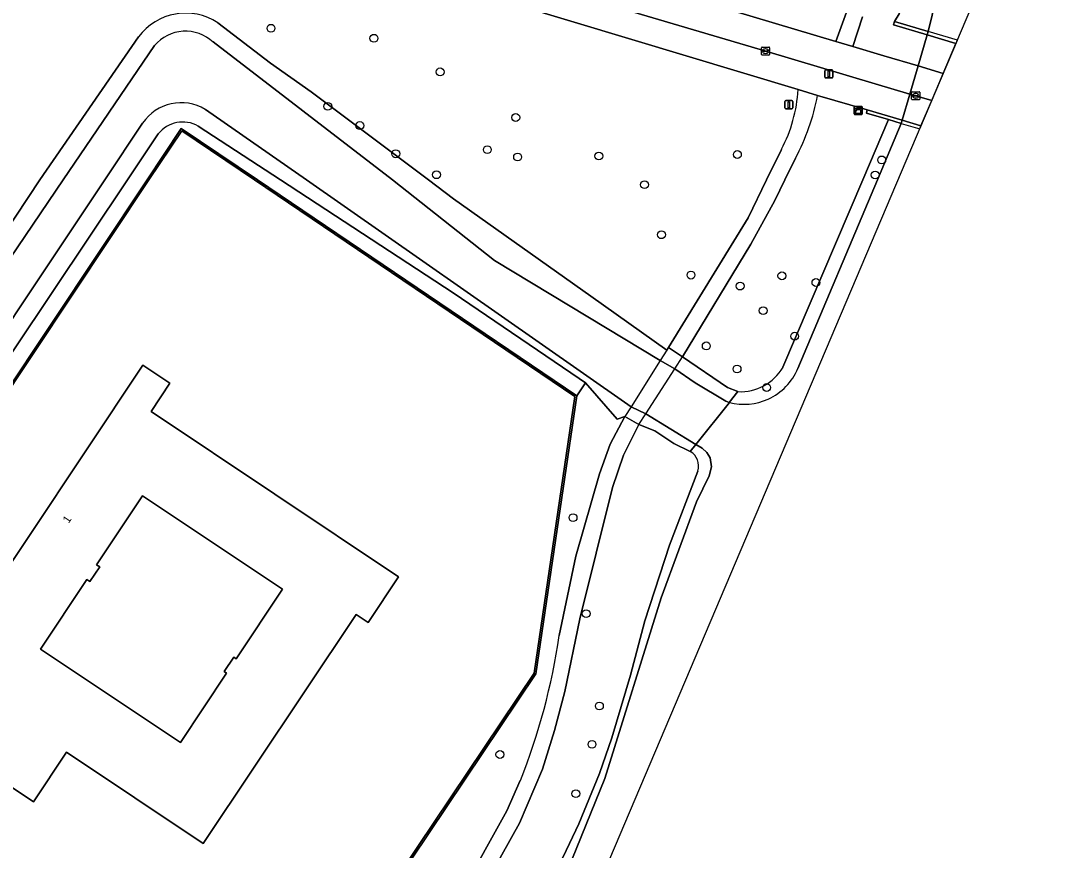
# Model space of a CAD drawing. Extents: x 160157 to 160921, y 381516 to 382045.
# Drawn here: x 160791.5 to 160921, y 381666.3 to 381769.9 of the extents above; entities that cross this region are included whole.
import ezdxf

# ---------------------------------------------------------------- set-up
doc = ezdxf.new("R2010")
doc.units = 0
for name, color, linetype in [('IMGEO_Berm_groen', 7, 'Continuous'), ('IMGEO_Boom', 7, 'Continuous'), ('IMGEO_Dek', 7, 'Continuous'), ('IMGEO_Erf', 7, 'Continuous'), ('IMGEO_Fietspad_gesloten', 7, 'Continuous'), ('IMGEO_Fietspad_open', 7, 'Continuous'), ('IMGEO_Grasland_overig', 7, 'Continuous'), ('IMGEO_Groenvoorziening', 7, 'Continuous'), ('IMGEO_Kast', 7, 'Continuous'), ('IMGEO_Kolk', 7, 'Continuous'), ('IMGEO_Lichtmast', 7, 'Continuous'), ('IMGEO_Loofbos', 7, 'Continuous'), ('IMGEO_Muur', 7, 'Continuous'), ('IMGEO_Oever', 7, 'Continuous'), ('IMGEO_Pand', 7, 'Continuous'), ('IMGEO_Pand_nummerreeks', 7, 'Continuous'), ('IMGEO_Verkeersbordpaal', 7, 'Continuous'), ('IMGEO_Voetpad_gesloten', 7, 'Continuous'), ('IMGEO_Voetpad_open', 7, 'Continuous'), ('IMGEO_Waterloop', 7, 'Continuous')]:
    doc.layers.add(name, color=color, linetype=linetype)

msp = doc.modelspace()

# ---------------------------------------------------------------- linework, layer by layer
at = {"layer": 'IMGEO_Berm_groen'}
for points in [[(160823.24, 381789.06), (160836.93, 381784.15), (160893.31, 381767.3), (160894.66, 381770.94)], [(160896.67, 381770.38), (160895.43, 381766.66), (160899.33, 381765.5), (160903.6, 381764.23), (160904.74, 381768.11), (160900.52, 381769.38), (160900.65, 381769.8), (160901.23, 381770.74), (160904.69, 381783.05), (160904.31, 381786.03)]]:
    msp.add_lwpolyline(points, dxfattribs=at)
msp.add_lwpolyline([(160906.74, 381763.29), (160908.33, 381767.03), (160904.74, 381768.11), (160903.6, 381764.23)], close=True, dxfattribs=at)
at = {"layer": 'IMGEO_Boom'}
for centre in [(160822.76, 381768.94), (160835.62, 381767.69), (160843.89, 381763.49), (160829.86, 381759.19), (160853.34, 381757.8), (160833.86, 381756.79), (160849.79, 381753.78), (160838.35, 381753.27), (160853.57, 381752.86), (160863.72, 381752.99), (160881.03, 381753.17), (160899.06, 381752.5), (160843.44, 381750.65), (160898.24, 381750.62), (160869.43, 381749.41), (160871.54, 381743.16), (160875.23, 381738.12), (160886.59, 381738.03), (160881.37, 381736.75), (160890.84, 381737.19), (160884.25, 381733.68), (160888.18, 381730.49), (160877.14, 381729.28), (160880.99, 381726.39), (160884.68, 381724.08), (160860.5, 381707.84), (160862.13, 381695.85), (160863.79, 381684.32), (160862.87, 381679.53), (160851.36, 381678.26), (160860.85, 381673.37)]:
    msp.add_circle(centre, 0.489, dxfattribs=at)
at = {"layer": 'IMGEO_Dek'}
for points in [[(160903.8, 381756.38), (160908.51, 381767.45), (160908.51, 381767.45), (160904.87, 381768.54), (160904.74, 381768.11), (160903.6, 381764.23), (160902.56, 381760.73), (160901.6, 381757.46), (160901.48, 381757.06)], [(160873.2, 381726.4), (160874.19, 381727.93), (160872.42, 381729.06), (160872.22, 381728.75), (160871.4, 381727.46), (160867.75, 381721.69), (160866.97, 381720.46), (160868.73, 381719.46), (160869.6, 381720.8)]]:
    msp.add_lwpolyline(points, close=True, dxfattribs=at)
at = {"layer": 'IMGEO_Erf'}
for points in [[(160860.74, 381722.95), (160820.71, 381750), (160811.61, 381756.15), (160807.52, 381750), (160783.35, 381713.75), (160783.57, 381713.6), (160780.89, 381709.53), (160780.66, 381709.64), (160746.07, 381658.25), (160790.57, 381616.68), (160820.21, 381635.63), (160855.65, 381688.4)], [(160838.71, 381700.46), (160834.9, 381694.76), (160833.4, 381695.76), (160814.29, 381667.15), (160797.21, 381678.55), (160793.08, 381672.36), (160782.77, 381679.24), (160786.86, 381685.37), (160778.89, 381690.69), (160780.07, 381692.46), (160777.63, 381694.09), (160779.06, 381696.23), (160781.46, 381694.63), (160782.65, 381696.41), (160785.26, 381694.66), (160806.77, 381726.87), (160810.13, 381724.62), (160807.78, 381721.1)], [(160824.21, 381698.89), (160806.73, 381710.56), (160800.98, 381701.95), (160801.38, 381701.69), (160800.15, 381699.85), (160799.77, 381700.11), (160793.97, 381691.42), (160811.44, 381679.76), (160817.21, 381688.4), (160816.9, 381688.61), (160818.11, 381690.42), (160818.42, 381690.21)]]:
    msp.add_lwpolyline(points, close=True, dxfattribs=at)
at = {"layer": 'IMGEO_Fietspad_gesloten'}
msp.add_lwpolyline([(160905.31, 381759.91), (160906.74, 381763.29), (160903.6, 381764.23), (160902.56, 381760.73)], close=True, dxfattribs=at)
at = {"layer": 'IMGEO_Fietspad_open'}
msp.add_lwpolyline([(160820.77, 381786.23), (160825.69, 381784.41), (160838.2, 381780.05), (160845.08, 381777.86), (160864.68, 381771.96), (160884.57, 381766.08), (160898.25, 381762.01), (160902.56, 381760.73), (160903.6, 381764.23), (160899.33, 381765.5), (160895.43, 381766.66), (160893.31, 381767.3), (160836.93, 381784.15), (160823.24, 381789.06)], dxfattribs=at)
at = {"layer": 'IMGEO_Grasland_overig'}
for points in [[(160886.72, 381726.62), (160896.7, 381750), (160899.91, 381757.53), (160897.17, 381758.34), (160897.25, 381758.77), (160891.04, 381760.56)], [(160888.28, 381752.71), (160886.96, 381750), (160885.71, 381747.43), (160882.69, 381742), (160874.19, 381727.93), (160879.78, 381724.07), (160881.1, 381723.58)]]:
    msp.add_lwpolyline(points, dxfattribs=at)
for centre, radius, start, end in [((160863.94, 381765.69), 27.58, 331.9381, 349.2835), ((160881.42, 381729.7), 6.14, 267.0172, 329.8247)]:
    msp.add_arc(centre, radius, start, end, dxfattribs=at)
at = {"layer": 'IMGEO_Groenvoorziening'}
for points in [[(160845.52, 381735.91), (160823.96, 381750), (160813.67, 381756.72)], [(160808.67, 381755.74), (160804.82, 381750), (160781.27, 381714.84), (160782.76, 381713.72), (160782.96, 381714.02), (160783.19, 381713.86), (160807.28, 381750), (160811.56, 381756.43), (160821.07, 381750), (160860.96, 381723.05), (160862.07, 381724.67), (160861.27, 381725.22), (160845.52, 381735.91)], [(160860.83, 381703.04), (160863.81, 381713.3), (160865.13, 381716.99), (160866.97, 381720.46), (160866.02, 381720.14), (160862.07, 381724.67), (160860.96, 381723.05), (160855.84, 381688.32), (160820.35, 381635.48), (160790.55, 381616.43), (160789.53, 381615.69), (160791.95, 381613.46), (160793.53, 381614), (160806.92, 381622.08), (160812.28, 381625.56), (160815.77, 381628.23), (160833.62, 381644.48), (160837.29, 381648.09), (160840.52, 381652.1), (160846.58, 381661.03), (160852.21, 381671.21), (160853.91, 381675.02)], [(160875.14, 381716.09), (160873.1, 381717.09), (160870.72, 381718.69), (160868.73, 381719.46), (160866.82, 381715.63), (160865.41, 381711.6), (160861.34, 381695.19), (160859.49, 381686.11), (160858.2, 381681.25), (160856.69, 381676.45), (160853.81, 381669.7), (160848.2, 381659.61), (160842.12, 381651.05), (160838.4, 381646.23), (160843.55, 381645.32), (160851.86, 381653.79), (160854.68, 381657.51), (160857.15, 381661.47), (160859.28, 381665.49), (160861.24, 381669.59), (160863.79, 381675.87), (160865.35, 381680.36), (160867.68, 381688.15)], [(160867.68, 381688.15), (160869.48, 381694.94), (160872.54, 381704.38), (160876.09, 381713.66)], [(160858.78, 381693.12), (160860.83, 381703.04)]]:
    msp.add_lwpolyline(points, dxfattribs=at)
for centre, radius, start, end in [((160811.75, 381753.29), 3.94, 60.7744, 141.4883), ((160874.11, 381714.29), 2.08, 342.1586, 60.1244), ((160778.3, 381705.04), 81.36, 338.3447, 351.5735)]:
    msp.add_arc(centre, radius, start, end, dxfattribs=at)
at = {"layer": 'IMGEO_Kast'}
for p, q in [((160895.62, 381758.26), (160895.62, 381759.1)), ((160895.62, 381759.1), (160895.62, 381758.26)), ((160895.69, 381759.18), (160896.54, 381759.18)), ((160896.54, 381759.18), (160895.69, 381759.18)), ((160896.62, 381759.11), (160896.62, 381758.27)), ((160896.62, 381758.27), (160896.62, 381759.11)), ((160896.55, 381758.18), (160895.7, 381758.18)), ((160895.7, 381758.18), (160896.55, 381758.18))]:
    msp.add_line(p, q, dxfattribs=at)
for points in [[(160895.82, 381758.97), (160896.42, 381758.97), (160896.42, 381758.89), (160895.82, 381758.89), (160895.82, 381758.97)], [(160895.82, 381758.8), (160896.42, 381758.8), (160896.42, 381758.31), (160895.82, 381758.31), (160895.82, 381758.8)]]:
    msp.add_lwpolyline(points, dxfattribs=at)
msp.add_circle((160895.9, 381758.65), 0.0377, dxfattribs=at)
for centre, start, end in [((160895.7, 381759.1), 92.4484, 184.2845), ((160895.7, 381759.1), 92.4484, 184.2845), ((160896.54, 381759.1), 2.4484, 94.2845), ((160896.54, 381759.1), 2.4484, 94.2845), ((160895.7, 381758.26), 182.4484, 274.2845), ((160895.7, 381758.26), 182.4484, 274.2845), ((160896.54, 381758.26), 272.4484, 4.2845), ((160896.54, 381758.26), 272.4484, 4.2845)]:
    msp.add_arc(centre, 0.0779, start, end, dxfattribs=at)
at = {"layer": 'IMGEO_Kolk'}
for p, q in [((160884.05, 381765.66), (160884.05, 381766.51)), ((160884.12, 381766.59), (160884.97, 381766.59)), ((160884.97, 381765.58), (160884.12, 381765.58)), ((160884.3, 381766.08), (160884.3, 381766.09)), ((160884.74, 381766.04), (160884.34, 381766.04)), ((160884.35, 381766.13), (160884.74, 381766.13)), ((160884.53, 381766.36), (160884.56, 381766.36)), ((160884.56, 381765.81), (160884.53, 381765.81)), ((160884.79, 381766.09), (160884.79, 381766.08)), ((160885.05, 381766.51), (160885.05, 381765.66)), ((160902.8, 381760.08), (160902.8, 381760.94)), ((160902.88, 381761.01), (160903.73, 381761.01)), ((160903.06, 381760.5), (160903.06, 381760.52)), ((160903.5, 381760.47), (160903.1, 381760.47)), ((160903.11, 381760.55), (160903.5, 381760.55)), ((160903.29, 381760.79), (160903.32, 381760.79)), ((160903.55, 381760.52), (160903.55, 381760.5)), ((160903.81, 381760.94), (160903.81, 381760.08)), ((160903.73, 381760.01), (160902.88, 381760.01)), ((160903.31, 381760.23), (160903.29, 381760.23))]:
    msp.add_line(p, q, dxfattribs=at)
for points in [[(160884.05, 381765.66), (160884.05, 381766.51)], [(160884.12, 381766.59), (160884.97, 381766.59)], [(160884.97, 381765.58), (160884.12, 381765.58)], [(160885.05, 381766.51), (160885.05, 381765.66)], [(160902.8, 381760.08), (160902.8, 381760.94)], [(160902.88, 381761.01), (160903.73, 381761.01)], [(160903.81, 381760.94), (160903.81, 381760.08)], [(160903.73, 381760.01), (160902.88, 381760.01)]]:
    msp.add_lwpolyline(points, dxfattribs=at)
for centre, radius, start, end in [((160884.12, 381766.51), 0.0765, 91.552, 178.448), ((160884.12, 381766.51), 0.0765, 91.552, 178.448), ((160884.12, 381765.66), 0.0765, 181.552, 268.448), ((160884.12, 381765.66), 0.0765, 181.552, 268.448), ((160884.34, 381766.09), 0.0403, 85.8775, 175.7526), ((160884.34, 381766.08), 0.0366, 178.938, 274.7102), ((160884.75, 381766.09), 0.0386, 1.7309, 96.639), ((160884.75, 381766.08), 0.043, 264.8664, 352.4533), ((160884.97, 381766.51), 0.0765, 1.552, 88.448), ((160884.97, 381766.51), 0.0765, 1.552, 88.448), ((160884.97, 381765.66), 0.0765, 271.552, 358.448), ((160884.97, 381765.66), 0.0765, 271.552, 358.448), ((160902.88, 381760.93), 0.0765, 91.552, 178.448), ((160902.88, 381760.93), 0.0765, 91.552, 178.448), ((160903.1, 381760.51), 0.0403, 85.8775, 175.7526), ((160903.1, 381760.5), 0.0366, 178.938, 274.7102), ((160903.51, 381760.51), 0.0386, 1.7309, 96.639), ((160903.5, 381760.51), 0.043, 264.8664, 352.4533), ((160903.73, 381760.93), 0.0765, 1.552, 88.448), ((160903.73, 381760.93), 0.0765, 1.552, 88.448), ((160902.88, 381760.09), 0.0765, 181.552, 268.448), ((160902.88, 381760.09), 0.0765, 181.552, 268.448), ((160903.73, 381760.09), 0.0765, 271.552, 358.448), ((160903.73, 381760.09), 0.0765, 271.552, 358.448)]:
    msp.add_arc(centre, radius, start, end, dxfattribs=at)
for centre, major_axis, ratio, start_param, end_param in [((160884.53, 381766.08), (-0.387, 0.002), 0.722429, 4.712389, 7.853982), ((160884.56, 381766.08), (-0.39, 0.002), 0.717154, 1.570796, 4.712389), ((160903.29, 381760.51), (-0.387, 0.002), 0.722429, 4.712389, 7.853982), ((160903.32, 381760.51), (-0.39, 0.002), 0.717154, 1.570796, 4.712389)]:
    msp.add_ellipse(centre, major_axis=major_axis, ratio=ratio, start_param=start_param, end_param=end_param, dxfattribs=at)
at = {"layer": 'IMGEO_Lichtmast'}
for p, q in [((160891.96, 381762.84), (160891.96, 381763.64)), ((160891.96, 381763.64), (160891.96, 381762.84)), ((160892.06, 381763.74), (160892.85, 381763.74)), ((160892.85, 381763.74), (160892.06, 381763.74)), ((160892.95, 381763.64), (160892.95, 381762.84)), ((160892.95, 381762.84), (160892.95, 381763.64)), ((160892.85, 381762.74), (160892.06, 381762.74)), ((160892.06, 381762.74), (160892.85, 381762.74))]:
    msp.add_line(p, q, dxfattribs=at)
msp.add_lwpolyline([(160892.38, 381763.62), (160892.53, 381763.62), (160892.53, 381762.87), (160892.38, 381762.87), (160892.38, 381763.62)], dxfattribs=at)
for centre, start, end in [((160892.06, 381763.64), 90, 180), ((160892.06, 381763.64), 90, 180), ((160892.85, 381763.64), 0, 90), ((160892.85, 381763.64), 360, 90), ((160892.06, 381762.84), 180, 270), ((160892.06, 381762.84), 180, 270), ((160892.85, 381762.84), 270, 0), ((160892.85, 381762.84), 270, 0)]:
    msp.add_arc(centre, 0.1, start, end, dxfattribs=at)
at = {"layer": 'IMGEO_Loofbos'}
for points in [[(160798.59, 381790.38), (160797.76, 381789.74), (160795.51, 381787.72), (160792.76, 381789.48), (160791.43, 381788.02), (160767.52, 381753.72), (160764.92, 381750), (160753.58, 381733.81), (160755.22, 381732.74), (160764.09, 381726.92), (160772.58, 381721.3), (160774.15, 381720.21), (160793.89, 381750), (160806.2, 381767.87)], [(160888.61, 381761.28), (160839.44, 381776.11), (160820.7, 381782.66), (160805.66, 381788.42), (160801.4, 381790.42)], [(160816.13, 381769.62), (160822.7, 381764.59), (160827.8, 381761.01), (160842.45, 381750), (160845.57, 381747.65), (160862.73, 381735.48), (160872.22, 381728.75), (160872.42, 381729.06), (160882.38, 381745.29), (160884.67, 381750), (160886.53, 381753.82)]]:
    msp.add_lwpolyline(points, dxfattribs=at)
for centre, radius, start, end in [((160812.1, 381763.47), 7.36, 56.7615, 143.3065), ((160870.48, 381762.31), 18.16, 332.1383, 356.7516)]:
    msp.add_arc(centre, radius, start, end, dxfattribs=at)
at = {"layer": 'IMGEO_Muur'}
for points in [[(160900.65, 381769.8), (160900.52, 381769.38), (160904.74, 381768.11), (160904.87, 381768.54)], [(160908.51, 381767.45), (160908.51, 381767.45), (160904.87, 381768.54), (160904.74, 381768.11), (160908.33, 381767.03)], [(160897.25, 381758.77), (160897.17, 381758.34), (160899.91, 381757.53), (160901.48, 381757.06), (160901.6, 381757.46)], [(160903.96, 381756.75), (160901.6, 381757.46), (160901.48, 381757.06), (160903.8, 381756.38)], [(160821.07, 381750), (160811.56, 381756.43), (160807.28, 381750), (160783.19, 381713.86), (160783.35, 381713.75), (160807.52, 381750), (160811.61, 381756.15), (160820.71, 381750), (160860.74, 381722.95), (160855.65, 381688.4), (160820.21, 381635.63), (160790.57, 381616.68), (160746.07, 381658.25), (160780.66, 381709.64), (160780.48, 381709.73), (160745.81, 381658.22), (160790.55, 381616.43), (160820.35, 381635.48), (160855.84, 381688.32), (160860.96, 381723.05)]]:
    msp.add_lwpolyline(points, close=True, dxfattribs=at)
at = {"layer": 'IMGEO_Oever'}
msp.add_lwpolyline([(160911.32, 381792.4), (160907.63, 381793.53), (160904.69, 381783.05), (160901.23, 381770.74), (160900.65, 381769.8), (160904.87, 381768.54), (160906.31, 381774.51)], close=True, dxfattribs=at)
for points in [[(160880.02, 381722.23), (160881.1, 381723.58), (160879.78, 381724.07), (160874.19, 381727.93), (160872.42, 381729.06), (160872.22, 381728.75), (160862.73, 381735.48), (160845.57, 381747.65), (160842.45, 381750), (160827.8, 381761.01), (160822.7, 381764.59), (160816.13, 381769.62)], [(160806.2, 381767.87), (160793.89, 381750), (160774.15, 381720.21), (160775.76, 381719), (160796.82, 381750), (160808.22, 381766.79)], [(160815.52, 381767.23), (160837.93, 381750), (160850.68, 381739.95), (160862.36, 381732.91), (160871.4, 381727.46), (160873.2, 381726.4), (160875.76, 381724.65), (160879.58, 381722.36), (160879.8, 381722.29), (160880.02, 381722.23)], [(160875.14, 381716.09), (160875.84, 381716.97), (160869.6, 381720.8), (160867.75, 381721.69), (160861.4, 381726.12), (160827.18, 381750), (160814.56, 381758.8)], [(160806.73, 381757.1), (160801.99, 381750), (160779.43, 381716.23), (160781.27, 381714.84), (160804.82, 381750), (160808.67, 381755.74)], [(160813.67, 381756.72), (160823.96, 381750), (160845.52, 381735.91), (160861.27, 381725.22), (160862.07, 381724.67), (160866.02, 381720.14), (160866.97, 381720.46), (160868.73, 381719.46), (160870.72, 381718.69), (160873.1, 381717.09), (160875.14, 381716.09)], [(160901.48, 381757.06), (160899.91, 381757.53), (160896.7, 381750), (160886.72, 381726.62)], [(160888.57, 381726.47), (160898.54, 381750), (160901.48, 381757.06)], [(160881.1, 381723.58), (160880.02, 381722.23), (160880.03, 381722.23)], [(160800.26, 381605.88), (160812.69, 381614.8), (160818.68, 381619.39), (160824.35, 381624.7), (160830.52, 381630.47), (160847.44, 381647), (160854.41, 381655.52), (160858.26, 381660.7), (160859.19, 381662.23), (160864.45, 381675.26), (160871.51, 381697.83), (160875.93, 381709.79), (160877.51, 381713.07), (160877.78, 381714.17), (160877.63, 381715.3), (160877.2, 381715.96), (160876.61, 381716.5), (160875.85, 381716.96), (160875.84, 381716.97), (160875.14, 381716.09)], [(160876.09, 381713.66), (160872.54, 381704.38), (160869.48, 381694.94), (160867.68, 381688.15), (160865.35, 381680.36), (160863.79, 381675.87), (160861.24, 381669.59), (160859.28, 381665.49), (160857.15, 381661.47), (160854.68, 381657.51), (160851.86, 381653.79), (160843.55, 381645.32), (160829.6, 381631.5), (160821.82, 381624.23), (160818.15, 381621.1), (160815.79, 381618.73), (160813.53, 381617.06), (160809.43, 381614.59), (160800.34, 381607.9)]]:
    msp.add_lwpolyline(points, dxfattribs=at)
for centre, radius, start, end in [((160812.1, 381763.47), 7.36, 56.7615, 143.3065), ((160812.08, 381763.55), 5.03, 46.8692, 140.0303), ((160811.53, 381753.85), 5.8, 58.5511, 145.945), ((160811.75, 381753.29), 3.94, 60.7744, 141.4883), ((160881.42, 381729.7), 6.14, 267.0172, 329.8247), ((160881.88, 381729.23), 7.24, 294.5608, 337.5901), ((160881.87, 381729.23), 7.24, 255.3183, 294.5997), ((160874.11, 381714.29), 2.08, 342.1586, 60.1244)]:
    msp.add_arc(centre, radius, start, end, dxfattribs=at)
at = {"layer": 'IMGEO_Pand'}
for points in [[(160833.4, 381695.76), (160834.9, 381694.76), (160838.71, 381700.46), (160807.78, 381721.1), (160810.13, 381724.62), (160806.77, 381726.87), (160785.26, 381694.66), (160782.65, 381696.41), (160781.46, 381694.63), (160779.06, 381696.23), (160777.63, 381694.09), (160780.07, 381692.46), (160778.89, 381690.69), (160786.86, 381685.37), (160782.77, 381679.24), (160793.08, 381672.36), (160797.21, 381678.55), (160814.29, 381667.15)], [(160799.77, 381700.11), (160800.15, 381699.85), (160801.38, 381701.69), (160800.98, 381701.95), (160806.73, 381710.56), (160824.21, 381698.89), (160818.42, 381690.21), (160818.11, 381690.42), (160816.9, 381688.61), (160817.21, 381688.4), (160811.44, 381679.76), (160793.97, 381691.42)]]:
    msp.add_lwpolyline(points, close=True, dxfattribs=at)
at = {"layer": 'IMGEO_Verkeersbordpaal'}
for p, q in [((160886.96, 381759), (160886.96, 381759.8)), ((160886.96, 381759.8), (160886.96, 381759)), ((160887.06, 381759.9), (160887.85, 381759.9)), ((160887.85, 381759.9), (160887.06, 381759.9)), ((160887.95, 381759.8), (160887.95, 381759)), ((160887.95, 381759), (160887.95, 381759.8)), ((160887.85, 381758.9), (160887.06, 381758.9)), ((160887.06, 381758.9), (160887.85, 381758.9))]:
    msp.add_line(p, q, dxfattribs=at)
msp.add_lwpolyline([(160887.38, 381759.77), (160887.53, 381759.77), (160887.53, 381759.02), (160887.38, 381759.02), (160887.38, 381759.77)], dxfattribs=at)
for centre, start, end in [((160887.06, 381759.8), 90, 180), ((160887.06, 381759.8), 90, 180), ((160887.85, 381759.8), 0, 90), ((160887.85, 381759.8), 360, 90), ((160887.06, 381759), 180, 270), ((160887.06, 381759), 180, 270), ((160887.85, 381759), 270, 0), ((160887.85, 381759), 270, 0)]:
    msp.add_arc(centre, 0.1, start, end, dxfattribs=at)
at = {"layer": 'IMGEO_Voetpad_gesloten'}
for points in [[(160891.04, 381760.56), (160888.61, 381761.28)], [(160886.53, 381753.82), (160884.67, 381750), (160882.38, 381745.29), (160872.42, 381729.06), (160874.19, 381727.93), (160882.69, 381742), (160885.71, 381747.43), (160886.96, 381750), (160888.28, 381752.71)], [(160810.37, 381621.8), (160816.14, 381625.62), (160821.18, 381629.94), (160838.4, 381646.23), (160842.12, 381651.05), (160848.2, 381659.61), (160853.81, 381669.7), (160856.69, 381676.45), (160858.2, 381681.25), (160859.49, 381686.11), (160861.34, 381695.19), (160865.41, 381711.6), (160866.82, 381715.63), (160868.73, 381719.46), (160866.97, 381720.46), (160865.13, 381716.99), (160863.81, 381713.3), (160860.83, 381703.04), (160858.78, 381693.12)], [(160853.91, 381675.02), (160852.21, 381671.21), (160846.58, 381661.03), (160840.52, 381652.1), (160837.29, 381648.09), (160833.62, 381644.48), (160815.77, 381628.23), (160812.28, 381625.56), (160806.92, 381622.08), (160793.53, 381614), (160791.95, 381613.46), (160791.56, 381613.33), (160791.58, 381613.07), (160792.92, 381611.91), (160793.01, 381611.67), (160793.58, 381612.11), (160796.34, 381613.41), (160802.5, 381616.82), (160810.37, 381621.8)]]:
    msp.add_lwpolyline(points, dxfattribs=at)
msp.add_lwpolyline([(160873.2, 381726.4), (160874.19, 381727.93), (160872.42, 381729.06), (160872.22, 381728.75), (160871.4, 381727.46), (160867.75, 381721.69), (160866.97, 381720.46), (160868.73, 381719.46), (160869.6, 381720.8)], close=True, dxfattribs=at)
for centre, radius, start, end in [((160870.48, 381762.31), 18.16, 332.1383, 356.7516), ((160863.94, 381765.69), 27.58, 331.9381, 349.2835), ((160778.3, 381705.04), 81.36, 338.3447, 351.5735)]:
    msp.add_arc(centre, radius, start, end, dxfattribs=at)
at = {"layer": 'IMGEO_Voetpad_open'}
for points in [[(160801.4, 381790.42), (160805.66, 381788.42), (160820.7, 381782.66), (160839.44, 381776.11), (160888.61, 381761.28), (160891.04, 381760.56), (160897.25, 381758.77), (160901.6, 381757.46), (160902.56, 381760.73), (160898.25, 381762.01), (160884.57, 381766.08), (160864.68, 381771.96), (160845.08, 381777.86)], [(160894.66, 381770.94), (160893.31, 381767.3), (160895.43, 381766.66), (160896.67, 381770.38)]]:
    msp.add_lwpolyline(points, dxfattribs=at)
msp.add_lwpolyline([(160905.31, 381759.91), (160902.56, 381760.73), (160901.6, 381757.46), (160903.96, 381756.75)], close=True, dxfattribs=at)
at = {"layer": 'IMGEO_Waterloop'}
for points in [[(160775.77, 381559.99), (160807.03, 381606.26), (160859.46, 381652.02), (160920.99, 381796.82), (160913.25, 381799.3), (160913.21, 381799.16), (160913, 381798.38), (160912.77, 381797.57), (160911.98, 381794.75), (160911.46, 381792.9), (160911.32, 381792.4), (160906.31, 381774.51), (160904.87, 381768.54), (160904.74, 381768.11), (160903.6, 381764.23), (160902.56, 381760.73), (160901.6, 381757.46), (160901.48, 381757.06), (160898.54, 381750), (160888.57, 381726.47)], [(160814.56, 381758.8), (160827.18, 381750), (160861.4, 381726.12), (160867.75, 381721.69), (160869.6, 381720.8), (160875.84, 381716.97), (160875.85, 381716.96), (160880.03, 381722.23), (160880.02, 381722.23), (160879.8, 381722.29), (160879.58, 381722.36), (160875.76, 381724.65), (160873.2, 381726.4), (160871.4, 381727.46), (160862.36, 381732.91), (160850.68, 381739.95), (160837.93, 381750), (160815.52, 381767.23)], [(160808.22, 381766.79), (160796.82, 381750), (160775.76, 381719), (160775.56, 381718.69), (160773.59, 381715.62), (160773.42, 381715.35), (160736.36, 381661.51)], [(160777.45, 381712.45), (160777.61, 381712.77), (160779.27, 381715.92), (160779.43, 381716.23), (160801.99, 381750), (160806.73, 381757.1)], [(160880.03, 381722.23), (160875.85, 381716.96), (160876.61, 381716.5), (160877.2, 381715.96), (160877.63, 381715.3), (160877.78, 381714.17), (160877.51, 381713.07), (160875.93, 381709.79), (160871.51, 381697.83), (160864.45, 381675.26), (160859.19, 381662.23), (160858.26, 381660.7), (160854.41, 381655.52), (160847.44, 381647), (160830.52, 381630.47), (160824.35, 381624.7), (160818.68, 381619.39), (160812.69, 381614.8), (160800.26, 381605.88)]]:
    msp.add_lwpolyline(points, dxfattribs=at)
for centre, radius, start, end in [((160812.08, 381763.55), 5.03, 46.8692, 140.0303), ((160811.53, 381753.85), 5.8, 58.5511, 145.945), ((160881.88, 381729.23), 7.24, 294.5608, 337.5901), ((160881.87, 381729.23), 7.24, 255.3183, 294.5997)]:
    msp.add_arc(centre, radius, start, end, dxfattribs=at)

# ---------------------------------------------------------------- texts
at = {"layer": 'IMGEO_Pand_nummerreeks'}
msp.add_text('1', height=1, rotation=56.2722, dxfattribs=at).set_placement((160797.48, 381707.05))

doc.saveas('drawing.dxf')
